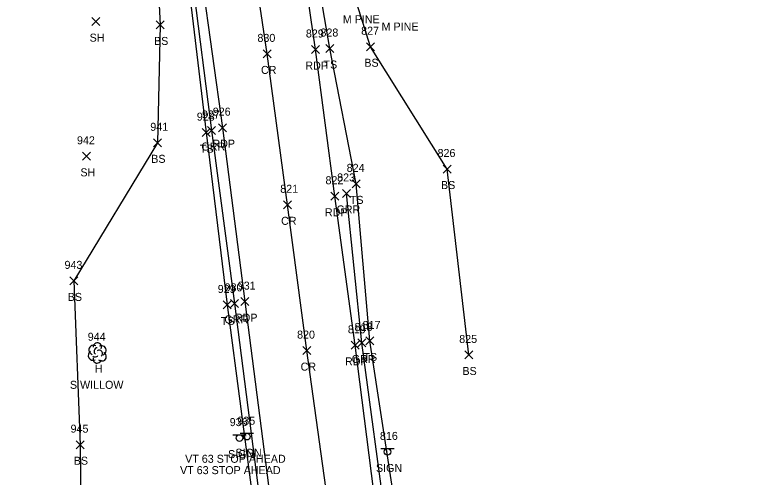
# Model space of a CAD drawing. Extents: x 1629176 to 1637209, y 606063 to 610167.
# Drawn here: x 1629888.9 to 1630075.4, y 607340.7 to 607456.1 of the extents above; entities that cross this region are included whole.
import ezdxf

# ---------------------------------------------------------------- set-up
doc = ezdxf.new("R2010")
doc.units = 0
for name, color, linetype in [('L_A', 7, 'Continuous'), ('L_C', 7, 'Continuous'), ('L_I', 7, 'Continuous'), ('L_TIC', 7, 'Continuous'), ('LELB', 7, 'Continuous'), ('LTD', 7, 'Continuous'), ('P_A', 7, 'Continuous'), ('P_I', 7, 'Continuous'), ('P_TIC', 7, 'Continuous'), ('PET', 7, 'Continuous'), ('PRC', 7, 'Continuous'), ('R_A', 7, 'Continuous'), ('R_I', 7, 'Continuous'), ('R_TIC', 7, 'Continuous'), ('RGR', 7, 'Continuous'), ('S_A', 7, 'Continuous'), ('S_C', 7, 'Continuous'), ('S_I', 7, 'Continuous'), ('SSGN', 7, 'Continuous')]:
    doc.layers.add(name, color=color, linetype=linetype)

msp = doc.modelspace()

# ---------------------------------------------------------------- linework, layer by layer
at = {"layer": 'L_TIC'}
for points in [[(1629908.04, 607453.4), (1629910.04, 607455.4)], [(1629910.04, 607453.4), (1629908.04, 607455.4)], [(1629924.16, 607452.58), (1629926.16, 607454.58)], [(1629926.16, 607452.58), (1629924.16, 607454.58)], [(1629976.69, 607447.13), (1629978.69, 607449.13)], [(1629978.69, 607447.13), (1629976.69, 607449.13)], [(1629966.52, 607446.68), (1629968.52, 607448.68)], [(1629968.52, 607446.68), (1629966.52, 607448.68)], [(1629935.65, 607425.68), (1629937.65, 607427.68)], [(1629937.65, 607425.68), (1629935.65, 607427.68)], [(1629923.47, 607423.14), (1629925.47, 607425.14)], [(1629925.47, 607423.14), (1629923.47, 607425.14)], [(1629905.72, 607419.77), (1629907.72, 607421.77)], [(1629907.72, 607419.77), (1629905.72, 607421.77)], [(1629995.83, 607416.59), (1629997.83, 607418.59)], [(1629997.83, 607416.59), (1629995.83, 607418.59)], [(1629973.09, 607412.89), (1629975.09, 607414.89)], [(1629975.09, 607412.89), (1629973.09, 607414.89)], [(1629902.61, 607388.66), (1629904.61, 607390.66)], [(1629904.61, 607388.66), (1629902.61, 607390.66)], [(1629940.88, 607382.65), (1629942.88, 607384.65)], [(1629942.88, 607382.65), (1629940.88, 607384.65)], [(1629976.49, 607373.66), (1629978.49, 607375.66)], [(1629978.49, 607373.66), (1629976.49, 607375.66)], [(1630001.18, 607370.16), (1630003.18, 607372.16)], [(1630003.18, 607370.16), (1630001.18, 607372.16)], [(1629904.12, 607347.76), (1629906.12, 607349.76)], [(1629906.12, 607347.76), (1629904.12, 607349.76)]]:
    msp.add_lwpolyline(points, dxfattribs=at)
at = {"layer": 'LELB'}
for points in [[(1629901.85, 607620.62), (1629912.64, 607607.29), (1629916.95, 607582.23), (1629921.84, 607547.23), (1629926.69, 607509.97), (1629926.47, 607496.41), (1629932.23, 607463.67), (1629936.65, 607426.68), (1629941.88, 607383.65), (1629948.66, 607331.72), (1629951.48, 607294.54)], [(1629872.74, 607605.4), (1629887.91, 607617.06), (1629901.2, 607617.32), (1629908.5, 607605.8), (1629913.9, 607581.78), (1629917.02, 607546.87), (1629916.16, 607509.81), (1629923.16, 607493.27), (1629925.16, 607453.58), (1629924.47, 607424.14), (1629903.61, 607389.66), (1629905.12, 607348.76), (1629905.7, 607299.56), (1629903.23, 607230.04), (1629906.81, 607190.46), (1629918.09, 607128.12), (1629917.39, 607086.84), (1629912.31, 607067.56), (1629894.57, 607057.72), (1629861.26, 607071.43), (1629823.99, 607082.84), (1629794.36, 607095.25), (1629802.79, 607128.03), (1629840.82, 607119.34)], [(1630084.2, 606935.53), (1630049.16, 606947.36), (1630020.53, 606959.33), (1630006.71, 606971.89), (1629998.15, 606985.2), (1629997.66, 607001.36), (1630003.56, 607031.17), (1630013.65, 607060.81), (1630014.9, 607093.95), (1630014.94, 607124.25), (1630010.97, 607149.73), (1630004.22, 607196.84), (1629997.94, 607243.02), (1629990.5, 607295.3), (1629983.84, 607333.53), (1629977.49, 607374.66), (1629974.09, 607413.89), (1629967.52, 607447.68), (1629960.93, 607485.98), (1629955.08, 607527.79), (1629952.27, 607562.54)], [(1630002.18, 607371.16), (1629996.83, 607417.59), (1629977.69, 607448.13), (1629965.59, 607486.49), (1629959.9, 607528.48), (1629952.27, 607562.54)]]:
    msp.add_lwpolyline(points, dxfattribs=at)
at = {"layer": 'LTD'}
msp.add_line((1629909.41, 607371.71), (1629909.41, 607371.71), dxfattribs=at)
msp.add_line((1629909.41, 607371.71), (1629909.41, 607371.71), dxfattribs=at)
msp.add_arc((1629909.45, 607373.14), 1.05, 335.5272, 180.9563, dxfattribs=at)
for centre, major_axis, ratio, start_param, end_param in [((1629908.62, 607372.38), (1.21, -0.51), 0.895232, 1.570796, 4.712389), ((1629909.2, 607372.17), (-0.208, -0.792), 0.645439, 3.141593, 6.283185), ((1629909.91, 607371.54), (-0.5, 0.667), 0.989748, 3.141593, 6.283185), ((1629910.45, 607372.29), (-1.14, -0.48), 0.949671, 1.570796, 4.712389), ((1629908.32, 607371), (0.58, -1.04), 0.959034, 3.141593, 6.283185), ((1629909.41, 607370.21), (0.26, 1.06), 0.942809, 1.570796, 4.712389), ((1629908.95, 607370.96), (-0.625, -0.083), 0.423636, 0, 3.141593), ((1629910.41, 607370.88), (-1.09, 0.79), 0.841452, 1.570796, 4.712389)]:
    msp.add_ellipse(centre, major_axis=major_axis, ratio=ratio, start_param=start_param, end_param=end_param, dxfattribs=at)
at = {"layer": 'P_TIC'}
for points in [[(1629950.88, 607445.34), (1629952.88, 607447.34)], [(1629952.88, 607445.34), (1629950.88, 607447.34)], [(1629962.89, 607446.44), (1629964.89, 607448.44)], [(1629964.89, 607446.44), (1629962.89, 607448.44)], [(1629939.69, 607426.92), (1629941.69, 607428.92)], [(1629941.69, 607426.92), (1629939.69, 607428.92)], [(1629967.79, 607409.79), (1629969.79, 607411.79)], [(1629969.79, 607409.79), (1629967.79, 607411.79)], [(1629955.91, 607407.66), (1629957.91, 607409.66)], [(1629957.91, 607407.66), (1629955.91, 607409.66)], [(1629945.3, 607383.48), (1629947.3, 607385.48)], [(1629947.3, 607383.48), (1629945.3, 607385.48)], [(1629972.81, 607372.57), (1629974.81, 607374.57)], [(1629974.81, 607372.57), (1629972.81, 607374.57)], [(1629960.78, 607371.25), (1629962.78, 607373.25)], [(1629962.78, 607371.25), (1629960.78, 607373.25)]]:
    msp.add_lwpolyline(points, dxfattribs=at)
at = {"layer": 'PET'}
for points in [[(1629979.67, 607327.82), (1629973.81, 607373.57), (1629968.79, 607410.79), (1629963.89, 607447.44), (1629958.35, 607485.82), (1629952.57, 607527.42), (1629949.09, 607558.98), (1629944.71, 607586.25), (1629940.16, 607615.76), (1629934.55, 607655.5), (1629928.02, 607704.49)], [(1629903.84, 607700.62), (1629910.61, 607651.05), (1629916.36, 607610.75), (1629919.9, 607582.29), (1629924.47, 607547.4), (1629929.48, 607509.85), (1629935.58, 607464.89), (1629940.69, 607427.92), (1629946.3, 607384.48), (1629952.98, 607332.78)]]:
    msp.add_lwpolyline(points, dxfattribs=at)
at = {"layer": 'PRC'}
msp.add_lwpolyline([(1629963.88, 606969.73), (1629972.76, 606997.52), (1629981.25, 607028.09), (1629988.12, 607066.47), (1629990.62, 607100.29), (1629990.61, 607124.69), (1629989.69, 607149.78), (1629986.77, 607182.68), (1629981.28, 607228.24), (1629975.13, 607276.5), (1629968.07, 607326.63), (1629961.78, 607372.25), (1629956.91, 607408.66), (1629951.88, 607446.34), (1629946.39, 607483.34), (1629940.59, 607526.71), (1629934.53, 607569.1), (1629928.23, 607613.94), (1629922.81, 607653.99), (1629916.48, 607702.82)], dxfattribs=at)
at = {"layer": 'R_TIC'}
for points in [[(1629936.95, 607426.21), (1629938.95, 607428.21)], [(1629938.95, 607426.21), (1629936.95, 607428.21)], [(1629970.69, 607410.49), (1629972.69, 607412.49)], [(1629972.69, 607410.49), (1629970.69, 607412.49)], [(1629942.69, 607383.05), (1629944.69, 607385.05)], [(1629944.69, 607383.05), (1629942.69, 607385.05)], [(1629974.48, 607373.16), (1629976.48, 607375.16)], [(1629976.48, 607373.16), (1629974.48, 607375.16)]]:
    msp.add_lwpolyline(points, dxfattribs=at)
at = {"layer": 'RGR'}
for points in [[(1629928.19, 607496.6), (1629933.22, 607464.46), (1629937.95, 607427.21), (1629943.69, 607384.05), (1629950.32, 607332.08)], [(1630115.67, 606918.76), (1630070.66, 606934.74), (1630047.22, 606943.05), (1630028.22, 606950.43), (1630014.62, 606957.76), (1630006.28, 606964.78), (1629999.39, 606973.89), (1629995.11, 606983.4), (1629993.57, 606992.79), (1629994.69, 607005.74), (1630000.61, 607035.72), (1630004.58, 607063.56), (1630005.51, 607096.84), (1630005.28, 607124.06), (1630003.63, 607150.96), (1629999.95, 607185.04), (1629994.67, 607228.89), (1629988.47, 607276.39), (1629981.73, 607327.94), (1629975.48, 607374.16), (1629971.69, 607411.49)]]:
    msp.add_lwpolyline(points, dxfattribs=at)
at = {"layer": 'SSGN'}
for p, q in [((1629943.3, 607351.25), (1629946.64, 607351.25)), ((1629944.95, 607350.42), (1629944.95, 607350.42)), ((1629945.15, 607351.61), (1629948.48, 607351.61)), ((1629946.8, 607350.77), (1629946.8, 607350.77)), ((1629980.24, 607347.81), (1629983.58, 607347.81)), ((1629981.89, 607346.97), (1629981.89, 607346.97))]:
    msp.add_line(p, q, dxfattribs=at)
for centre in [(1629944.95, 607350.42), (1629946.8, 607350.77), (1629981.89, 607346.97)]:
    msp.add_circle(centre, 0.833, dxfattribs=at)

# ---------------------------------------------------------------- texts
at = {"layer": 'L_A'}
for s, p in [('SH', (1629907.52, 607449.4)), ('BS', (1629923.6, 607448.58)), ('BS', (1629976.13, 607443.13)), ('TS', (1629965.93, 607442.68)), ('TS', (1629935.06, 607421.68)), ('BS', (1629922.91, 607419.14)), ('SH', (1629905.21, 607415.77)), ('BS', (1629995.27, 607412.59)), ('TS', (1629972.5, 607408.89)), ('BS', (1629902.05, 607384.66)), ('TS', (1629940.28, 607378.65)), ('TS', (1629975.9, 607369.66)), ('H', (1629908.84, 607366.71)), ('BS', (1630000.62, 607366.16)), ('BS', (1629903.56, 607343.76))]:
    msp.add_text(s, height=2, dxfattribs=at).set_placement(p)
at = {"layer": 'L_C'}
for s, p in [('M PINE', (1629970.74, 607453.99)), ('M PINE', (1629980.44, 607452.18)), ('S WILLOW', (1629902.6, 607362.71))]:
    msp.add_text(s, height=2, dxfattribs=at).set_placement(p)
at = {"layer": 'L_I'}
for s, p in [('828', (1629965.16, 607450.68)), ('827', (1629975.33, 607451.13)), ('928', (1629934.29, 607429.68)), ('941', (1629922.67, 607427.14)), ('942', (1629904.36, 607423.77)), ('826', (1629994.41, 607420.59)), ('824', (1629971.72, 607416.89)), ('943', (1629901.25, 607392.66)), ('929', (1629939.51, 607386.65)), ('817', (1629975.7, 607377.66)), ('944', (1629907.05, 607374.71)), ('825', (1629999.82, 607374.16)), ('945', (1629902.76, 607351.76))]:
    msp.add_text(s, height=2, dxfattribs=at).set_placement(p)
at = {"layer": 'P_A'}
for s, p in [('CR', (1629950.31, 607441.34)), ('RDP', (1629961.38, 607442.44)), ('RDP', (1629938.18, 607422.92)), ('RDP', (1629966.28, 607405.79)), ('CR', (1629955.34, 607403.66)), ('RDP', (1629943.79, 607379.48)), ('RDP', (1629971.3, 607368.57)), ('CR', (1629960.21, 607367.25))]:
    msp.add_text(s, height=2, dxfattribs=at).set_placement(p)
at = {"layer": 'P_I'}
for s, p in [('830', (1629949.43, 607449.34)), ('829', (1629961.52, 607450.44)), ('926', (1629938.27, 607430.92)), ('822', (1629966.43, 607413.79)), ('821', (1629955.12, 607411.66)), ('931', (1629944.51, 607387.48)), ('819', (1629972.01, 607376.57)), ('820', (1629959.33, 607375.25))]:
    msp.add_text(s, height=2, dxfattribs=at).set_placement(p)
at = {"layer": 'R_A'}
for p in [(1629935.43, 607422.21), (1629969.18, 607406.49), (1629941.18, 607379.05), (1629972.97, 607369.16)]:
    msp.add_text('GRR', height=2, dxfattribs=at).set_placement(p)
at = {"layer": 'R_I'}
for s, p in [('927', (1629935.58, 607430.21)), ('823', (1629969.33, 607414.49)), ('930', (1629941.24, 607387.05)), ('818', (1629973.68, 607377.16))]:
    msp.add_text(s, height=2, dxfattribs=at).set_placement(p)
at = {"layer": 'S_A'}
for p in [(1629942.09, 607345.4), (1629943.93, 607345.75), (1629979.03, 607341.95)]:
    msp.add_text('SIGN', height=2, dxfattribs=at).set_placement(p)
at = {"layer": 'S_C'}
for p in [(1629931.37, 607344.24), (1629930.1, 607341.4)]:
    msp.add_text('VT 63 STOP AHEAD', height=2, dxfattribs=at).set_placement(p)
at = {"layer": 'S_I'}
for s, p in [('935', (1629944.41, 607353.75)), ('936', (1629942.51, 607353.4)), ('816', (1629980.02, 607349.95))]:
    msp.add_text(s, height=2, dxfattribs=at).set_placement(p)

doc.saveas('drawing.dxf')
